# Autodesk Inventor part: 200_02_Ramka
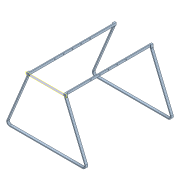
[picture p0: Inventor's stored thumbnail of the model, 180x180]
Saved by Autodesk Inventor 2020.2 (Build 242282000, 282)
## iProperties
Manager: www.cadconsulting.pl
Company: Fabian Stasiak CAD Consulting
Created: 2020-03
Part Number: 200_02_Ramka
Material: Stal
Document SubType Name: Modeling
Designer: F.Stasiak
Density: 7.85 g/cm^3
Appearance: Stalowoniebieska
Mass: 804.285 g
Surface Area: 718.428 cm^2
Volume: 102.457 cm^3
Catalog Web Link: www.expertbooks.pl
Author: F.Stasiak
Subject: Zbiór ćwiczeń. Autodesk Inventor 2020. Kurs Professional
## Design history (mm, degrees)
sketch "Szkic3"
  geometry: L1 (80, 200)-(-80, 200); L2 (-80, 200)-(-80, -200); L3 (-80, -200)-(80, -200); L4 (80, -200)-(80, 200); L5 (80, 200)-(-80, -200); L6 (-80, 200)-(80, -200); L7 (80, 200)-(84, 200); L8 (84, 200)-(84, -200); L9 (84, -200)-(80, -200); L10 (-80, 200)-(-84, 200); L11 (-84, 200)-(-84, -200); L12 (-84, -200)-(-80, -200); 1 further point
  constraints: 24 end point, 6 perpendicular, 3 parallel, 2 midpoint, 1 horizontal, 1 point on line
  dimensions: "d8" = 160 distance of L3.end L2.end; "d9" = 400 distance of L2.end L1.end; "d10" = 4 distance of L1.start L7.end; "d11" = 4 distance of L1.end L10.end (= d10)
extrude "Wyciągnięcie proste1" new body sketch "Szkic3" stored distance "d12" = 10; taper "d13" = 0 deg
node "Płaszczyzna konstrukcyjna1"
sketch "Szkic5"
  geometry: L1 (5, 0)-(5, -4) reference; L2 (5, -4)-(-8.011, -4); L3 (-11.838, -4.761)-(-231.173, -95.613); L4 (-245, -86.374)-(-245, 246.374); L5 (-231.173, 255.613)-(-11.838, 164.761); L6 (5, 160)-(5, 164) reference; L7 (-8.011, 164)-(5, 164); L8 (5, 168)-(-8.011, 168); L9 (-10.307, 168.457)-(-229.642, 259.308); L10 (-249, 246.374)-(-249, -86.374); L11 (-229.642, -99.308)-(-10.307, -8.457); L12 (-8.011, -8)-(5, -8); L13 (5, -4)-(5, -8); L14 (5, 164)-(5, 168); A1 r 10 centre (-8.011, 174) between (-11.838, 164.761) and (-8.011, 164); A2 r 10 centre (-8.011, -14) between (-8.011, -4) and (-11.838, -4.761); A3 r 10 centre (-235, -86.374) between (-245, -86.374) and (-231.173, -95.613); A4 r 10 centre (-235, 246.374) between (-231.173, 255.613) and (-245, 246.374); A5 r 6 centre (-8.011, 174) between (-10.307, 168.457) and (-8.011, 168); A6 r 14 centre (-235, 246.374) between (-229.642, 259.308) and (-249, 246.374); A7 r 14 centre (-235, -86.374) between (-249, -86.374) and (-229.642, -99.308); A8 r 6 centre (-8.011, -14) between (-8.011, -8) and (-10.307, -8.457); 3 further points
  constraints: 24 end point, 16 point on circle, 9 tangent, 8 centre point, 3 equal radius, 3 perpendicular, 3 point on line, 2 horizontal, 1 horizontal alignment, 1 midpoint, 1 parallel, 6 other
  dimensions: "d24" = 15 distance of L1.end point (-10, -4); "d25" = 250 distance from line of L6.end L4; "d26" = 10 radius of A1; "d27" = 45 deg angle of L5 L3; "d28" = 4 distance between parallel lines of L3 L11; "d29" = 4 distance of L1.end L12.end (= d28); "d30" = 4 distance of L6.end L8.start (= d28)
extrude "Wyciągnięcie proste3" join sketch "Szkic5" distance "d31" = 10; taper "d32" = 0 deg
mirror "Odbij2"
sketch "Szkic6"
  geometry: 1 further point
hole "Otwór1" sketch "Szkic6" at (190, 5) diameter "d33" = 4; stored, may be unused: countersink angle "d37" = 90 deg, drill point angle "d39" = 118 deg; dims "d34" = 6, "d35" = 4, "d36" = 2, "d38" = 8
pattern_linear "Szyk prostokątny1" dims "d42" = 40.1
node "Bryła1"
